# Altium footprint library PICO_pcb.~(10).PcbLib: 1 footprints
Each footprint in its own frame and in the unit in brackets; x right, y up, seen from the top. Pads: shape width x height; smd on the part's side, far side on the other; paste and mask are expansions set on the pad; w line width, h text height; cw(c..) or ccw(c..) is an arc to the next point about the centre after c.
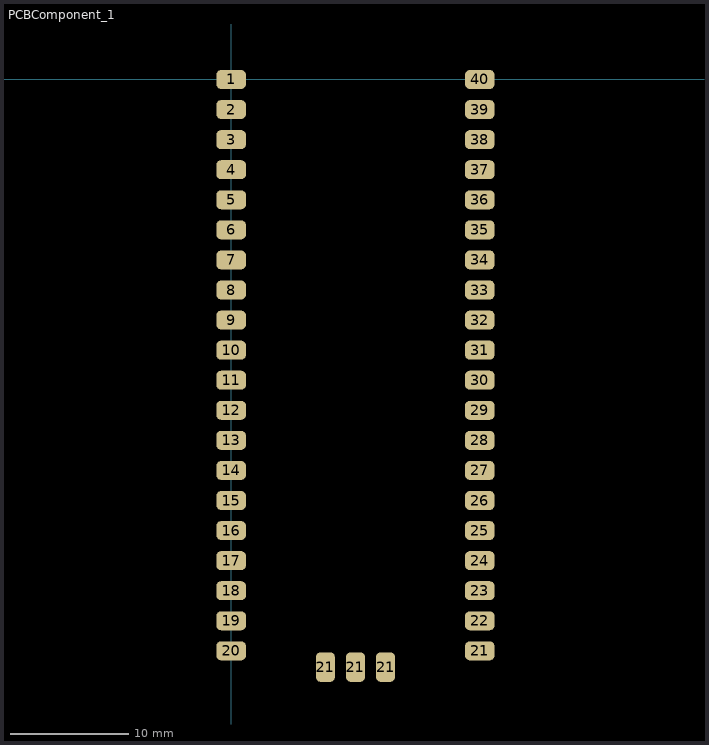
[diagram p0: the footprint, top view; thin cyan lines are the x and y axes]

## PCBComponent_1 [mm]
pads (43):
  rrect50% 2.5x1.6 smd: 1(0,0) 2(0,-2.54) 3(0,-5.08) 4(0,-7.62) 5(0,-10.16) 6(0,-12.7) 7(0,-15.24) 8(0,-17.78) 9(0,-20.32) 10(0,-22.86) 11(0,-25.4) 12(0,-27.94) 13(0,-30.48) 14(0,-33.02) 15(0,-35.56) 16(0,-38.1) 17(0,-40.64) 18(0,-43.18) 19(0,-45.72) 20(0,-48.26) 21(21,-48.26) 22(21,-45.72) 23(21,-43.18) 24(21,-40.64) 25(21,-38.1) 26(21,-35.56) 27(21,-33.02) 28(21,-30.48) 29(21,-27.94) 30(21,-25.4) 31(21,-22.86) 32(21,-20.32) 33(21,-17.78) 34(21,-15.24) 35(21,-12.7) 36(21,-10.16) 37(21,-7.62) 38(21,-5.08) 39(21,-2.54) 40(21,0)
  rrect50% 1.6x2.5 smd: 21(7.96,-49.63) 21(10.5,-49.63) 21(13.04,-49.63)
Bottom Overlay:
  lines w0.254: -3,-51.75 23.75,-51.75 ; -3,-51.75 -3,-51.75 ; -3,-51.75 -3,1.5 -2.5,2 23.75,2 23.75,-51.75 ; 23.75,-51.75 23.75,-51.75
3D body "Pico-R3.step": height 3.23, standoff -0.5, extent 0,-49.65 21,2.65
